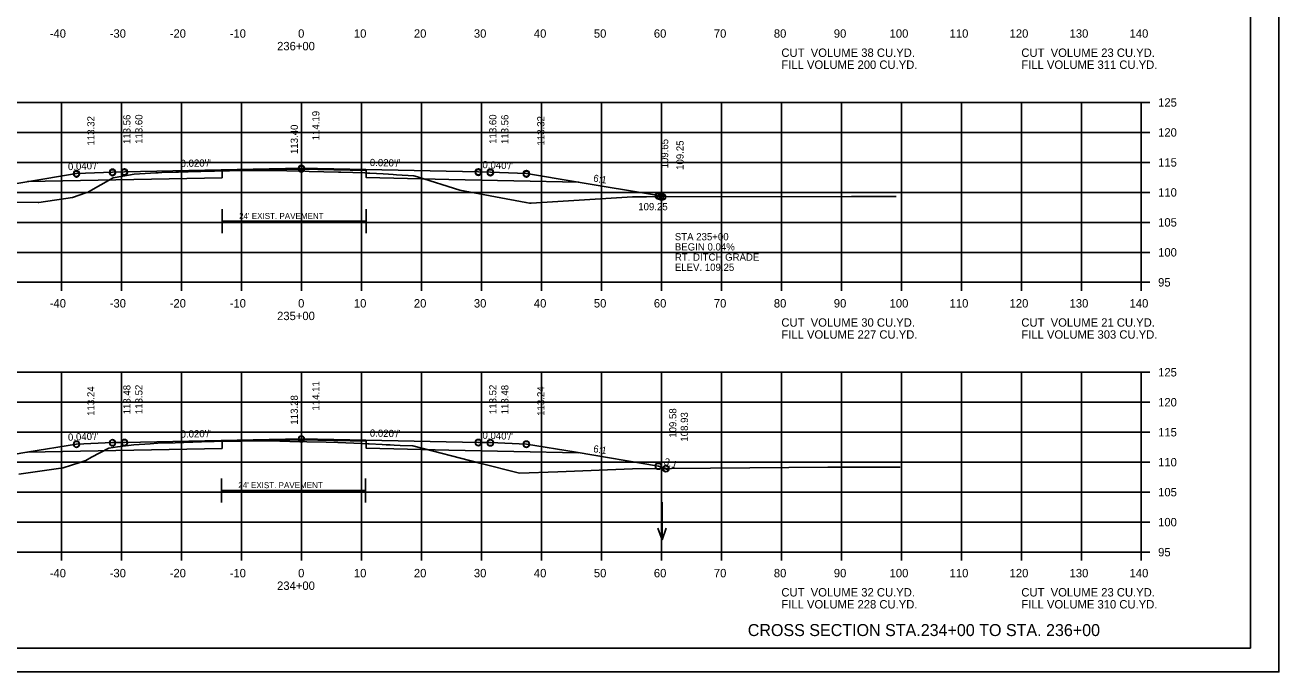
# Model space of a CAD drawing. Extents: x 1175611 to 1176402, y -433344 to -416213.
# Drawn here: x 1175734.9 to 1175943.9, y -422676.6 to -422568.7 of the extents above; entities that cross this region are included whole.
import ezdxf

# ---------------------------------------------------------------- set-up
doc = ezdxf.new("R2010")
doc.units = 0
for name, color, linetype in [('Default', 7, 'Continuous'), ('R_Alt Surface', 7, 'Continuous'), ('R_Axis', 7, 'Continuous'), ('R_Axis Annot', 7, 'Continuous'), ('R_Border', 7, 'Continuous'), ('R_Draft', 7, 'Continuous'), ('R_Exist Surface', 7, 'Continuous'), ('R_Fin Surface', 7, 'Continuous'), ('R_Grid', 7, 'Continuous'), ('R_No Plot', 7, 'Continuous'), ('R_Water', 7, 'Continuous'), ('R_Water Annot', 7, 'Continuous'), ('R_Xsect Elev', 7, 'Continuous'), ('R_Xsect Slope', 7, 'Continuous')]:
    doc.layers.add(name, color=color, linetype=linetype)

msp = doc.modelspace()

# ---------------------------------------------------------------- linework, layer by layer
at = {"layer": 'R_Alt Surface'}
for p, q in [((1175767.76, -422601.47), (1175791.76, -422601.47)), ((1175767.63, -422646.36), (1175791.63, -422646.36))]:
    msp.add_line(p, q, dxfattribs=at)
for points in [[(1175735.29, -422594.86), (1175767.74, -422594.21), (1175767.74, -422593.05), (1175780.97, -422592.79), (1175791.74, -422593), (1175791.74, -422594.16), (1175805.54, -422594.51), (1175827.19, -422594.94)], [(1175767.76, -422603.47), (1175767.76, -422599.47)], [(1175791.76, -422603.47), (1175791.76, -422599.47)], [(1175735.29, -422639.99), (1175767.74, -422639.34), (1175767.74, -422638.18), (1175780.97, -422637.92), (1175791.74, -422638.14), (1175791.74, -422639.29), (1175805.54, -422639.64), (1175827.19, -422640.08)], [(1175767.63, -422648.36), (1175767.63, -422644.36)], [(1175791.63, -422648.36), (1175791.63, -422644.36)]]:
    msp.add_lwpolyline(points, dxfattribs=at)
at = {"layer": 'R_Axis'}
for p, q in [((1175920.97, -422611.65), (1175920.97, -422581.65)), ((1175922.37, -422581.65), (1175920.97, -422581.65)), ((1175922.37, -422586.65), (1175920.97, -422586.65)), ((1175922.37, -422591.65), (1175920.97, -422591.65)), ((1175922.37, -422596.65), (1175920.97, -422596.65)), ((1175922.37, -422601.65), (1175920.97, -422601.65)), ((1175922.37, -422606.65), (1175920.97, -422606.65)), ((1175640.97, -422611.65), (1175920.97, -422611.65)), ((1175740.97, -422613.05), (1175740.97, -422611.65)), ((1175750.97, -422613.05), (1175750.97, -422611.65)), ((1175760.97, -422613.05), (1175760.97, -422611.65)), ((1175770.97, -422613.05), (1175770.97, -422611.65)), ((1175780.97, -422613.05), (1175780.97, -422611.65)), ((1175790.97, -422613.05), (1175790.97, -422611.65)), ((1175800.97, -422613.05), (1175800.97, -422611.65)), ((1175810.97, -422613.05), (1175810.97, -422611.65)), ((1175820.97, -422613.05), (1175820.97, -422611.65)), ((1175830.97, -422613.05), (1175830.97, -422611.65)), ((1175840.97, -422613.05), (1175840.97, -422611.65)), ((1175850.97, -422613.05), (1175850.97, -422611.65)), ((1175860.97, -422613.05), (1175860.97, -422611.65)), ((1175870.97, -422613.05), (1175870.97, -422611.65)), ((1175880.97, -422613.05), (1175880.97, -422611.65)), ((1175890.97, -422613.05), (1175890.97, -422611.65)), ((1175900.97, -422613.05), (1175900.97, -422611.65)), ((1175910.97, -422613.05), (1175910.97, -422611.65)), ((1175920.97, -422613.05), (1175920.97, -422611.65)), ((1175922.37, -422611.65), (1175920.97, -422611.65)), ((1175920.97, -422656.65), (1175920.97, -422626.65)), ((1175922.37, -422626.65), (1175920.97, -422626.65)), ((1175922.37, -422631.65), (1175920.97, -422631.65)), ((1175922.37, -422636.65), (1175920.97, -422636.65)), ((1175922.37, -422641.65), (1175920.97, -422641.65)), ((1175922.37, -422646.65), (1175920.97, -422646.65)), ((1175922.37, -422651.65), (1175920.97, -422651.65)), ((1175640.97, -422656.65), (1175920.97, -422656.65)), ((1175740.97, -422658.05), (1175740.97, -422656.65)), ((1175750.97, -422658.05), (1175750.97, -422656.65)), ((1175760.97, -422658.05), (1175760.97, -422656.65)), ((1175770.97, -422658.05), (1175770.97, -422656.65)), ((1175780.97, -422658.05), (1175780.97, -422656.65)), ((1175790.97, -422658.05), (1175790.97, -422656.65)), ((1175800.97, -422658.05), (1175800.97, -422656.65)), ((1175810.97, -422658.05), (1175810.97, -422656.65)), ((1175820.97, -422658.05), (1175820.97, -422656.65)), ((1175830.97, -422658.05), (1175830.97, -422656.65)), ((1175840.97, -422658.05), (1175840.97, -422656.65)), ((1175850.97, -422658.05), (1175850.97, -422656.65)), ((1175860.97, -422658.05), (1175860.97, -422656.65)), ((1175870.97, -422658.05), (1175870.97, -422656.65)), ((1175880.97, -422658.05), (1175880.97, -422656.65)), ((1175890.97, -422658.05), (1175890.97, -422656.65)), ((1175900.97, -422658.05), (1175900.97, -422656.65)), ((1175910.97, -422658.05), (1175910.97, -422656.65)), ((1175920.97, -422658.05), (1175920.97, -422656.65)), ((1175922.37, -422656.65), (1175920.97, -422656.65))]:
    msp.add_line(p, q, dxfattribs=at)
at = {"layer": 'R_Border'}
for q in [(1175939.15, -422467.19), (1175622.97, -422672.65)]:
    msp.add_line((1175939.15, -422672.65), q, dxfattribs=at)
at = {"layer": 'R_Exist Surface'}
for points in [[(1175715.27, -422598), (1175737.11, -422598.35), (1175737.16, -422598.35), (1175737.21, -422598.34), (1175742.78, -422597.49), (1175745.05, -422596.73), (1175745.29, -422596.65), (1175745.5, -422596.53), (1175749.57, -422594.24), (1175751.18, -422593.94), (1175753.1, -422593.61), (1175754.92, -422593.51), (1175756.69, -422593.4), (1175757.05, -422593.38), (1175757.08, -422593.38), (1175757.69, -422593.34), (1175760.05, -422593.28), (1175760.46, -422593.26), (1175763.73, -422593.16), (1175764.19, -422593.15), (1175768.75, -422593.04), (1175768.96, -422593.04), (1175770.2, -422593.01), (1175770.42, -422593), (1175775.14, -422592.99), (1175775.55, -422592.99), (1175781.53, -422593.12), (1175782.26, -422593.14), (1175787.15, -422593.27), (1175787.53, -422593.28), (1175791.51, -422593.41), (1175791.97, -422593.43), (1175792.37, -422593.45), (1175794.6, -422593.57), (1175795.49, -422593.62), (1175796.24, -422593.67), (1175796.8, -422593.71), (1175799.7, -422593.89), (1175800.29, -422594.08), (1175807.38, -422596.29), (1175818.38, -422598.33), (1175818.97, -422598.44), (1175819.26, -422598.43), (1175836.15, -422597.41), (1175838.46, -422597.41), (1175872.68, -422597.35), (1175876.85, -422597.36), (1175880.09, -422597.36)], [(1175733.88, -422643.64), (1175741.27, -422642.58), (1175744.03, -422641.69), (1175745.01, -422641.35), (1175745.99, -422640.83), (1175748.88, -422639.29), (1175750.31, -422639.09), (1175753.04, -422638.74), (1175755.76, -422638.57), (1175757.01, -422638.49), (1175759.92, -422638.4), (1175764.29, -422638.27), (1175766.44, -422638.22), (1175768.86, -422638.17), (1175769.99, -422638.14), (1175770.92, -422638.12), (1175773.66, -422638.11), (1175775.63, -422638.11), (1175779.06, -422638.18), (1175781.89, -422638.24), (1175785.09, -422638.33), (1175787.06, -422638.38), (1175789.69, -422638.47), (1175792.02, -422638.56), (1175792.28, -422638.57), (1175794.41, -422638.7), (1175795.1, -422638.74), (1175795.75, -422638.78), (1175796.45, -422638.81), (1175797.45, -422638.85), (1175799.55, -422638.92), (1175810.69, -422641.79), (1175817.34, -422643.5), (1175823.68, -422643.26), (1175836.13, -422642.77), (1175868.73, -422642.5), (1175873.18, -422642.47), (1175873.91, -422642.47), (1175880.76, -422642.47)]]:
    msp.add_lwpolyline(points, dxfattribs=at)
at = {"layer": 'R_Fin Surface'}
for points in [[(1175718.78, -422598.06), (1175721.47, -422597.16), (1175735.2, -422594.87), (1175743.47, -422593.49), (1175749.47, -422593.25), (1175751.47, -422593.21), (1175780.97, -422592.62), (1175810.47, -422593.21), (1175812.47, -422593.25), (1175818.47, -422593.49), (1175826.75, -422594.87), (1175840.47, -422597.16), (1175841.2, -422597.4)], [(1175718.73, -422643.2), (1175721.47, -422642.29), (1175735.2, -422640), (1175743.47, -422638.62), (1175749.47, -422638.38), (1175751.47, -422638.34), (1175780.97, -422637.75), (1175810.47, -422638.34), (1175812.47, -422638.38), (1175818.47, -422638.62), (1175826.75, -422640), (1175840.47, -422642.29), (1175841.77, -422642.72)]]:
    msp.add_lwpolyline(points, dxfattribs=at)
at = {"layer": 'R_Grid'}
for p, q in [((1175640.97, -422581.65), (1175920.97, -422581.65)), ((1175740.97, -422611.65), (1175740.97, -422581.65)), ((1175750.97, -422611.65), (1175750.97, -422581.65)), ((1175760.97, -422611.65), (1175760.97, -422581.65)), ((1175770.97, -422611.65), (1175770.97, -422581.65)), ((1175780.97, -422611.65), (1175780.97, -422581.65)), ((1175790.97, -422611.65), (1175790.97, -422581.65)), ((1175800.97, -422611.65), (1175800.97, -422581.65)), ((1175810.97, -422611.65), (1175810.97, -422581.65)), ((1175820.97, -422611.65), (1175820.97, -422581.65)), ((1175830.97, -422611.65), (1175830.97, -422581.65)), ((1175840.97, -422611.65), (1175840.97, -422581.65)), ((1175850.97, -422611.65), (1175850.97, -422581.65)), ((1175860.97, -422611.65), (1175860.97, -422581.65)), ((1175870.97, -422611.65), (1175870.97, -422581.65)), ((1175880.97, -422611.65), (1175880.97, -422581.65)), ((1175890.97, -422611.65), (1175890.97, -422581.65)), ((1175900.97, -422611.65), (1175900.97, -422581.65)), ((1175910.97, -422611.65), (1175910.97, -422581.65)), ((1175920.97, -422611.65), (1175920.97, -422581.65)), ((1175640.97, -422586.65), (1175920.97, -422586.65)), ((1175640.97, -422591.65), (1175920.97, -422591.65)), ((1175640.97, -422596.65), (1175920.97, -422596.65)), ((1175640.97, -422601.65), (1175920.97, -422601.65)), ((1175640.97, -422606.65), (1175920.97, -422606.65)), ((1175640.97, -422611.65), (1175920.97, -422611.65)), ((1175640.97, -422626.65), (1175920.97, -422626.65)), ((1175640.97, -422626.65), (1175920.97, -422626.65)), ((1175740.97, -422656.65), (1175740.97, -422626.65)), ((1175740.97, -422656.65), (1175740.97, -422626.65)), ((1175750.97, -422656.65), (1175750.97, -422626.65)), ((1175750.97, -422656.65), (1175750.97, -422626.65)), ((1175760.97, -422656.65), (1175760.97, -422626.65)), ((1175760.97, -422656.65), (1175760.97, -422626.65)), ((1175770.97, -422656.65), (1175770.97, -422626.65)), ((1175770.97, -422656.65), (1175770.97, -422626.65)), ((1175780.97, -422656.65), (1175780.97, -422626.65)), ((1175780.97, -422656.65), (1175780.97, -422626.65)), ((1175790.97, -422656.65), (1175790.97, -422626.65)), ((1175790.97, -422656.65), (1175790.97, -422626.65)), ((1175800.97, -422656.65), (1175800.97, -422626.65)), ((1175800.97, -422656.65), (1175800.97, -422626.65)), ((1175810.97, -422656.65), (1175810.97, -422626.65)), ((1175810.97, -422656.65), (1175810.97, -422626.65)), ((1175820.97, -422656.65), (1175820.97, -422626.65)), ((1175820.97, -422656.65), (1175820.97, -422626.65)), ((1175830.97, -422656.65), (1175830.97, -422626.65)), ((1175830.97, -422656.65), (1175830.97, -422626.65)), ((1175840.97, -422656.65), (1175840.97, -422626.65)), ((1175840.97, -422656.65), (1175840.97, -422626.65)), ((1175850.97, -422656.65), (1175850.97, -422626.65)), ((1175850.97, -422656.65), (1175850.97, -422626.65)), ((1175860.97, -422656.65), (1175860.97, -422626.65)), ((1175860.97, -422656.65), (1175860.97, -422626.65)), ((1175870.97, -422656.65), (1175870.97, -422626.65)), ((1175870.97, -422656.65), (1175870.97, -422626.65)), ((1175880.97, -422656.65), (1175880.97, -422626.65)), ((1175880.97, -422656.65), (1175880.97, -422626.65)), ((1175890.97, -422656.65), (1175890.97, -422626.65)), ((1175890.97, -422656.65), (1175890.97, -422626.65)), ((1175900.97, -422656.65), (1175900.97, -422626.65)), ((1175900.97, -422656.65), (1175900.97, -422626.65)), ((1175910.97, -422656.65), (1175910.97, -422626.65)), ((1175910.97, -422656.65), (1175910.97, -422626.65)), ((1175920.97, -422656.65), (1175920.97, -422626.65)), ((1175920.97, -422656.65), (1175920.97, -422626.65)), ((1175640.97, -422631.65), (1175920.97, -422631.65)), ((1175640.97, -422631.65), (1175920.97, -422631.65)), ((1175640.97, -422636.65), (1175920.97, -422636.65)), ((1175640.97, -422636.65), (1175920.97, -422636.65)), ((1175640.97, -422641.65), (1175920.97, -422641.65)), ((1175640.97, -422641.65), (1175920.97, -422641.65)), ((1175640.97, -422646.65), (1175920.97, -422646.65)), ((1175640.97, -422646.65), (1175920.97, -422646.65)), ((1175640.97, -422651.65), (1175920.97, -422651.65)), ((1175640.97, -422651.65), (1175920.97, -422651.65)), ((1175640.97, -422656.65), (1175920.97, -422656.65)), ((1175640.97, -422656.65), (1175920.97, -422656.65))]:
    msp.add_line(p, q, dxfattribs=at)
at = {"layer": 'R_No Plot'}
msp.add_line((1175610.57, -422676.63), (1175943.91, -422676.63), dxfattribs=at)
msp.add_lwpolyline([(1175610.57, -422463.3), (1175943.91, -422463.3), (1175943.91, -422676.63), (1175610.57, -422676.63)], close=True, dxfattribs=at)
for centre in [(1175743.47, -422593.49), (1175743.47, -422593.61), (1175749.47, -422593.25), (1175749.47, -422593.37), (1175751.47, -422593.21), (1175751.47, -422593.33), (1175780.97, -422592.62), (1175780.97, -422592.74), (1175810.47, -422593.21), (1175810.47, -422593.33), (1175812.47, -422593.25), (1175812.47, -422593.37), (1175818.47, -422593.49), (1175818.47, -422593.61), (1175840.47, -422597.16), (1175840.47, -422597.28), (1175840.84, -422597.4), (1175841.2, -422597.4), (1175841.2, -422597.4), (1175743.47, -422638.62), (1175743.47, -422638.68), (1175749.47, -422638.38), (1175749.47, -422638.44), (1175751.47, -422638.34), (1175751.47, -422638.4), (1175780.97, -422637.75), (1175780.97, -422637.81), (1175810.47, -422638.34), (1175810.47, -422638.4), (1175812.47, -422638.38), (1175812.47, -422638.44), (1175818.47, -422638.62), (1175818.47, -422638.68), (1175840.47, -422642.29), (1175840.47, -422642.34), (1175841.68, -422642.75), (1175841.75, -422642.72), (1175841.77, -422642.72), (1175841.77, -422642.72)]:
    msp.add_circle(centre, 0.5, dxfattribs=at)
at = {"layer": 'R_Water'}
for q in [(1175841.68, -422642.75), (1175842.39, -422642.72)]:
    msp.add_line((1175841.99, -422642.85), q, dxfattribs=at)
at = {"layer": 'R_Water Annot'}
for p, q in [((1175841.08, -422648.3), (1175841.08, -422654.59)), ((1175841.08, -422654.59), (1175840.38, -422652.66)), ((1175841.08, -422654.59), (1175841.78, -422652.66))]:
    msp.add_line(p, q, dxfattribs=at)

# ---------------------------------------------------------------- texts
at = {"layer": 'Default'}
for s, p in [('CUT  VOLUME 38 CU.YD.', (1175860.97, -422574.05)), ('CUT  VOLUME 23 CU.YD.', (1175900.97, -422574.05)), ('FILL VOLUME 200 CU.YD.', (1175860.97, -422576.05)), ('FILL VOLUME 311 CU.YD.', (1175900.97, -422576.05)), ('CUT  VOLUME 30 CU.YD.', (1175860.97, -422619.05)), ('CUT  VOLUME 21 CU.YD.', (1175900.97, -422619.05)), ('FILL VOLUME 227 CU.YD.', (1175860.97, -422621.05)), ('FILL VOLUME 303 CU.YD.', (1175900.97, -422621.05)), ('CUT  VOLUME 32 CU.YD.', (1175860.97, -422664.05)), ('CUT  VOLUME 23 CU.YD.', (1175900.97, -422664.05)), ('FILL VOLUME 228 CU.YD.', (1175860.97, -422666.05)), ('FILL VOLUME 310 CU.YD.', (1175900.97, -422666.05))]:
    msp.add_text(s, height=1.4, dxfattribs=at).set_placement(p)
at = {"layer": 'R_Alt Surface'}
for p in [(1175770.58, -422601.08), (1175770.44, -422645.98)]:
    msp.add_text("24' EXIST. PAVEMENT", height=1, dxfattribs=at).set_placement(p)
at = {"layer": 'R_Axis Annot'}
for s, p in [('-40', (1175739.01, -422570.85)), ('-30', (1175749.01, -422570.85)), ('-20', (1175759.01, -422570.85)), ('-10', (1175769.01, -422570.85)), ('0', (1175780.41, -422570.85)), ('10', (1175789.71, -422570.85)), ('20', (1175799.71, -422570.85)), ('30', (1175809.71, -422570.85)), ('40', (1175819.71, -422570.85)), ('50', (1175829.71, -422570.85)), ('60', (1175839.71, -422570.85)), ('70', (1175849.71, -422570.85)), ('80', (1175859.71, -422570.85)), ('90', (1175869.71, -422570.85)), ('100', (1175879.01, -422570.85)), ('110', (1175889.01, -422570.85)), ('120', (1175899.01, -422570.85)), ('130', (1175909.01, -422570.85)), ('140', (1175919.01, -422570.85)), ('236+00', (1175776.91, -422572.95)), ('125', (1175923.77, -422582.35)), ('120', (1175923.77, -422587.35)), ('115', (1175923.77, -422592.35)), ('110', (1175923.77, -422597.35)), ('105', (1175923.77, -422602.35)), ('100', (1175923.77, -422607.35)), ('95', (1175923.77, -422612.35)), ('-40', (1175739.01, -422615.85)), ('-30', (1175749.01, -422615.85)), ('-20', (1175759.01, -422615.85)), ('-10', (1175769.01, -422615.85)), ('0', (1175780.41, -422615.85)), ('10', (1175789.71, -422615.85)), ('20', (1175799.71, -422615.85)), ('30', (1175809.71, -422615.85)), ('40', (1175819.71, -422615.85)), ('50', (1175829.71, -422615.85)), ('60', (1175839.71, -422615.85)), ('70', (1175849.71, -422615.85)), ('80', (1175859.71, -422615.85)), ('90', (1175869.71, -422615.85)), ('100', (1175879.01, -422615.85)), ('110', (1175889.01, -422615.85)), ('120', (1175899.01, -422615.85)), ('130', (1175909.01, -422615.85)), ('140', (1175919.01, -422615.85)), ('235+00', (1175776.91, -422617.95)), ('125', (1175923.77, -422627.35)), ('120', (1175923.77, -422632.35)), ('115', (1175923.77, -422637.35)), ('110', (1175923.77, -422642.35)), ('105', (1175923.77, -422647.35)), ('100', (1175923.77, -422652.35)), ('95', (1175923.77, -422657.35)), ('-40', (1175739.01, -422660.85)), ('-30', (1175749.01, -422660.85)), ('-20', (1175759.01, -422660.85)), ('-10', (1175769.01, -422660.85)), ('0', (1175780.41, -422660.85)), ('10', (1175789.71, -422660.85)), ('20', (1175799.71, -422660.85)), ('30', (1175809.71, -422660.85)), ('40', (1175819.71, -422660.85)), ('50', (1175829.71, -422660.85)), ('60', (1175839.71, -422660.85)), ('70', (1175849.71, -422660.85)), ('80', (1175859.71, -422660.85)), ('90', (1175869.71, -422660.85)), ('100', (1175879.01, -422660.85)), ('110', (1175889.01, -422660.85)), ('120', (1175899.01, -422660.85)), ('130', (1175909.01, -422660.85)), ('140', (1175919.01, -422660.85)), ('234+00', (1175776.91, -422662.95))]:
    msp.add_text(s, height=1.4, dxfattribs=at).set_placement(p)
at = {"layer": 'R_Draft'}
msp.add_text('CROSS SECTION STA.234+00 TO STA. 236+00', height=2, dxfattribs=at).set_placement((1175855.37, -422670.65))
at = {"layer": 'R_Water Annot'}
for s, p in [('STA 235+00', (1175843.21, -422604.64)), ('BEGIN 0.04%', (1175843.21, -422606.34)), ('RT. DITCH GRADE', (1175843.21, -422608.04)), ('ELEV. 109.25', (1175843.21, -422609.74))]:
    msp.add_text(s, height=1.2, dxfattribs=at).set_placement(p)
at = {"layer": 'R_Xsect Elev'}
for s, p in [('113.32', (1175746.47, -422588.83)), ('113.56', (1175752.47, -422588.59)), ('113.60', (1175754.47, -422588.55)), ('114.19', (1175783.97, -422587.96)), ('113.60', (1175813.47, -422588.55)), ('113.56', (1175815.47, -422588.59)), ('113.32', (1175821.47, -422588.83)), ('113.40', (1175780.37, -422590.25)), ('109.65', (1175842.11, -422592.65)), ('109.25', (1175844.67, -422592.9)), ('113.52', (1175754.47, -422633.63)), ('114.11', (1175783.97, -422633.04)), ('113.52', (1175813.47, -422633.63)), ('113.24', (1175746.47, -422633.91)), ('113.48', (1175752.47, -422633.67)), ('113.28', (1175780.37, -422635.38)), ('113.48', (1175815.47, -422633.67)), ('113.24', (1175821.47, -422633.91)), ('109.58', (1175843.47, -422637.57)), ('108.93', (1175845.4, -422638.22))]:
    msp.add_text(s, height=1.2, rotation=90, dxfattribs=at).set_placement(p)
msp.add_text('109.25', height=1.2, dxfattribs=at).set_placement((1175837.11, -422599.63))
at = {"layer": 'R_Xsect Slope'}
for s, rotation, p in [("0.020'/'", 1.1458, (1175760.83, -422592.42)), ("0.020'/'", 358.8542, (1175792.36, -422592.25)), ("0.040'/'", 2.2906, (1175742.07, -422592.95)), ("0.040'/'", 357.7094, (1175811.12, -422592.6)), ('6:1', 350.5377, (1175829.55, -422594.83)), ("0.040'/'", 2.2906, (1175742.07, -422638.08)), ("0.020'/'", 1.1458, (1175760.83, -422637.56)), ("0.020'/'", 358.8542, (1175792.36, -422637.38)), ("0.040'/'", 357.7094, (1175811.12, -422637.73)), ('6:1', 350.5377, (1175829.55, -422639.96)), ('3:1', 341.5651, (1175841.28, -422642.03))]:
    msp.add_text(s, height=1.2, rotation=rotation, dxfattribs=at).set_placement(p)

doc.saveas('drawing.dxf')
